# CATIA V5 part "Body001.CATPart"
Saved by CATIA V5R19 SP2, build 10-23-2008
Part number: Body001
Definition: design
Nomenclature: Body001
Source: Unknown
Bounding box of the stored display mesh (mm): x -59 to 59, y -3 to 0, z -17 to 17
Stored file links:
  Z:\fausse table rondelle-20220905T211342Z-001\fausse table rondelle\Body001.CATPart
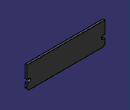
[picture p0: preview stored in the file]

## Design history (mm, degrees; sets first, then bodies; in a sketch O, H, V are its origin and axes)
AxisSystem1: origin (0, 0, 0), X (1, 0, 0), Y (0, 1, 0), Z (0, 0, 1)
Body1 "MANIFOLD_SOLID_BREP #5497" (main body)
  Solid1: solid without history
